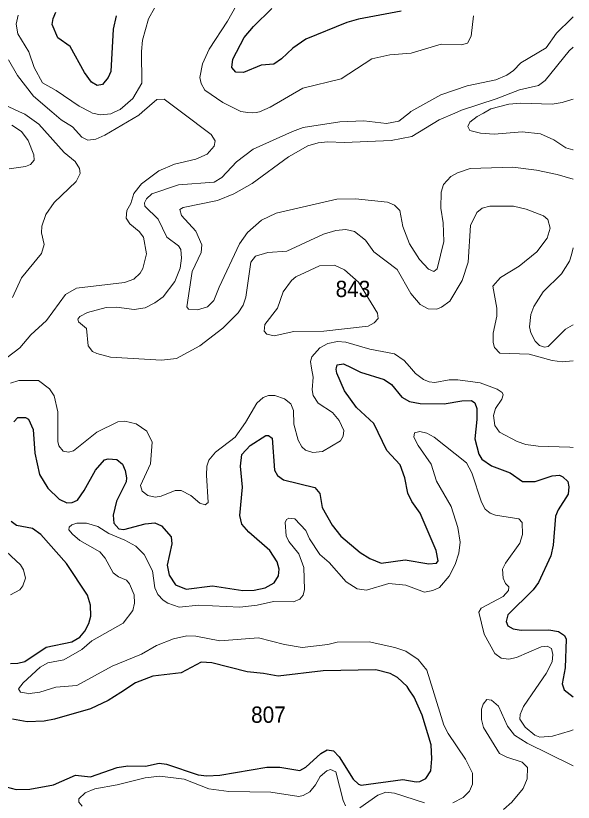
# Model space of a CAD drawing. Extents: x 473.9 to 500, y 7733.1 to 7760.8.
# Drawn here: x 497.268 to 500, y 7749.235 to 7753.088 of the extents above; entities that cross this region are included whole.
import ezdxf

# ---------------------------------------------------------------- set-up
doc = ezdxf.new("R2010")
doc.units = 0
doc.header["$LTSCALE"] = 0.032
doc.layers.add('1', color=7, linetype='Continuous', lineweight=25)
doc.layers.add('2', color=7, linetype='Continuous', lineweight=13)
doc.layers.add('21', color=7, linetype='Continuous')

msp = doc.modelspace()

# ---------------------------------------------------------------- linework, layer by layer
at = {"layer": '1'}
for points in [[(499.156, 7753.1103), (498.9468, 7753.0713), (498.8898, 7753.0552), (498.6902, 7752.9731), (498.6264, 7752.9292), (498.5701, 7752.8759), (498.5325, 7752.8503), (498.4698, 7752.8462), (498.3835, 7752.8103), (498.347, 7752.8107), (498.3273, 7752.8336), (498.3314, 7752.875), (498.3874, 7752.9803), (498.433, 7753.0351), (498.5221, 7753.1231)], [(497.7601, 7753.088), (497.7457, 7753.0212), (497.7334, 7752.8147), (497.7215, 7752.7859), (497.6934, 7752.7515), (497.667, 7752.7463), (497.6385, 7752.7631), (497.605, 7752.8093), (497.5349, 7752.9366), (497.4744, 7752.9793), (497.4469, 7753.0441), (497.4507, 7753.0734), (497.4647, 7753.1049)], [(499.1763, 7750.4223), (499.2926, 7750.4031), (499.329, 7750.4065), (499.3385, 7750.4175), (499.3286, 7750.4687), (499.2497, 7750.6503), (499.2096, 7750.7081), (499.1889, 7750.7494), (499.1751, 7750.824), (499.1514, 7750.8883), (499.0867, 7750.9575), (499.0231, 7751.0908), (498.938, 7751.1688), (498.8793, 7751.2502), (498.8413, 7751.3367), (498.838, 7751.3557), (498.8396, 7751.3631), (498.8426, 7751.3771), (498.8746, 7751.3821), (498.9117, 7751.3644), (498.9573, 7751.3425), (499.073, 7751.3062), (499.1087, 7751.281), (499.1606, 7751.2193), (499.1978, 7751.1974), (499.2491, 7751.1884), (499.3666, 7751.1862), (499.4542, 7751.2016), (499.501, 7751.2029), (499.5182, 7751.1919), (499.5267, 7751.1642), (499.5276, 7751.1106), (499.5182, 7751.0149), (499.5369, 7750.9398), (499.5523, 7750.9157), (499.5991, 7750.8836), (499.6915, 7750.8489), (499.7513, 7750.806), (499.8131, 7750.8059), (499.8968, 7750.8332), (499.932, 7750.8364), (499.9489, 7750.8298), (499.973, 7750.8058), (499.9787, 7750.7793), (499.9756, 7750.7446), (499.9252, 7750.6674), (499.9126, 7750.6366), (499.9014, 7750.4941), (499.8903, 7750.4423), (499.8302, 7750.312), (499.8034, 7750.2761), (499.6786, 7750.1527), (499.6715, 7750.1197), (499.6793, 7750.0996), (499.7059, 7750.0843), (499.7439, 7750.0775), (499.8806, 7750.0802), (499.9272, 7750.0709), (499.9572, 7750.0512), (499.9651, 7750.0342), (499.9595, 7749.894), (499.9458, 7749.8143), (499.9555, 7749.7854), (500, 7749.751)], [(497.258, 7751.0977), (497.2787, 7751.1202), (497.315, 7751.12), (497.3305, 7751.1107), (497.3537, 7751.0601), (497.3613, 7750.9448), (497.3836, 7750.84), (497.4246, 7750.7731), (497.4802, 7750.7192), (497.5175, 7750.7014), (497.5451, 7750.7032), (497.5698, 7750.7155), (497.6039, 7750.7622), (497.658, 7750.8624), (497.7026, 7750.912), (497.7203, 7750.917), (497.7632, 7750.9144), (497.7908, 7750.8915), (497.8046, 7750.8597), (497.8109, 7750.8246), (497.8082, 7750.8052), (497.7614, 7750.7094), (497.7452, 7750.641), (497.7478, 7750.6017), (497.7723, 7750.5751), (497.7976, 7750.5711), (497.9016, 7750.5981), (497.9488, 7750.6032), (497.982, 7750.5887), (498.0296, 7750.5356), (498.0321, 7750.5015), (498.0091, 7750.3961), (498.0202, 7750.3469), (498.0502, 7750.3002), (498.1027, 7750.2791), (498.2314, 7750.2946), (498.3806, 7750.2722), (498.4364, 7750.2738), (498.4893, 7750.2853), (498.5335, 7750.3094), (498.5555, 7750.3443), (498.5595, 7750.3767), (498.5485, 7750.4122), (498.5123, 7750.4675), (498.4104, 7750.5579), (498.3753, 7750.5972), (498.3659, 7750.6388), (498.3787, 7750.7787), (498.3692, 7750.8809), (498.3757, 7750.9378), (498.416, 7750.9828), (498.4927, 7751.0309), (498.5057, 7751.0307), (498.5236, 7751.0191), (498.5361, 7750.8618), (498.5504, 7750.8352), (498.5796, 7750.8141), (498.7337, 7750.7765), (498.7587, 7750.7466), (498.7689, 7750.6791), (498.8186, 7750.592), (498.8614, 7750.5386), (498.9555, 7750.4589), (499.0038, 7750.429), (499.0582, 7750.4063), (499.1763, 7750.4223)], [(497.2421, 7749.9153), (497.2775, 7749.9157), (497.3126, 7749.9247), (497.4161, 7749.9939), (497.5421, 7750.0207), (497.5811, 7750.0429), (497.6056, 7750.0724), (497.6253, 7750.1105), (497.6351, 7750.1471), (497.6348, 7750.2001), (497.6189, 7750.2487), (497.516, 7750.4038), (497.3913, 7750.5469), (497.3504, 7750.5754), (497.2723, 7750.5902), (497.2453, 7750.6096)], [(497.221, 7749.3104), (497.2695, 7749.2977), (497.337, 7749.2983), (497.4522, 7749.3198), (497.5613, 7749.3679), (497.6346, 7749.3587), (497.7645, 7749.4052), (497.8169, 7749.4133), (497.9043, 7749.4118), (497.9713, 7749.426), (498.0069, 7749.421), (498.1616, 7749.3699), (498.2049, 7749.3638), (498.2672, 7749.3673), (498.4977, 7749.4076), (498.5621, 7749.4076), (498.6594, 7749.3899), (498.6896, 7749.406), (498.7636, 7749.474), (498.7947, 7749.491), (498.8252, 7749.4871), (498.8527, 7749.4579), (498.9215, 7749.3475), (498.9472, 7749.3231), (498.961, 7749.3186), (499.1653, 7749.3472), (499.2305, 7749.3348), (499.2481, 7749.3369), (499.2773, 7749.3512), (499.3018, 7749.3886), (499.3074, 7749.4475), (499.3029, 7749.516), (499.2588, 7749.6621), (499.2207, 7749.7499), (499.1964, 7749.7861), (499.1857, 7749.802), (499.138, 7749.8455), (499.1032, 7749.866), (499.0318, 7749.8841), (498.7737, 7749.8795), (498.554, 7749.8524), (498.4826, 7749.866), (498.4025, 7749.873), (498.2292, 7749.9182), (498.1762, 7749.9214), (498.078, 7749.8692), (497.9391, 7749.8522), (497.8544, 7749.8206), (497.7821, 7749.7729), (497.721, 7749.7326), (497.6339, 7749.6928), (497.4575, 7749.6418), (497.4067, 7749.6322), (497.3232, 7749.6288), (497.2526, 7749.6416)]]:
    msp.add_lwpolyline(points, dxfattribs=at)
at = {"layer": '2'}
for points in [[(499.5107, 7753.0879), (499.5001, 7752.9877), (499.4809, 7752.9536), (499.4529, 7752.9446), (499.3522, 7752.9478), (499.2051, 7752.904), (499.1008, 7752.8963), (499.0132, 7752.8765), (498.8621, 7752.7779), (498.6752, 7752.7333), (498.5146, 7752.6391), (498.4623, 7752.6166), (498.4453, 7752.6142), (498.428, 7752.6118), (498.4057, 7752.6143), (498.3702, 7752.6184), (498.2834, 7752.6623), (498.1947, 7752.7236), (498.1772, 7752.7552), (498.1697, 7752.7851), (498.1834, 7752.8521), (498.2164, 7752.9244), (498.3056, 7753.0618), (498.39, 7753.2123)], [(497.9487, 7753.1282), (497.9182, 7753.0723), (497.8897, 7752.9685), (497.8843, 7752.9127), (497.8856, 7752.7569), (497.8412, 7752.6829), (497.7793, 7752.6282), (497.7533, 7752.6164), (497.7339, 7752.6075), (497.683, 7752.6021), (497.6444, 7752.6107), (497.6327, 7752.6167), (497.579, 7752.6443), (497.4659, 7752.7223), (497.3985, 7752.7598), (497.3582, 7752.8334), (497.3312, 7752.9115), (497.2777, 7752.999), (497.2692, 7753.0472), (497.279, 7753.09)], [(497.3816, 7752.557), (497.3127, 7752.6061), (497.2866, 7752.6178), (497.1761, 7752.6673), (497.1512, 7752.6865), (497.0837, 7752.7953), (497.0645, 7752.852), (497.0497, 7752.9648), (497.0587, 7753.0514), (497.041, 7753.1089)], [(500, 7751.3971), (499.9461, 7751.3924), (499.8971, 7751.3987), (499.7831, 7751.4297), (499.6393, 7751.4344), (499.6133, 7751.4624), (499.6072, 7751.4874), (499.6076, 7751.5324), (499.6249, 7751.6155), (499.6257, 7751.6554), (499.6062, 7751.763), (499.6432, 7751.8047), (499.7348, 7751.8603), (499.8219, 7751.9306), (499.8722, 7751.9977), (499.8869, 7752.0464), (499.8751, 7752.0888), (499.854, 7752.108), (499.7691, 7752.1407), (499.7073, 7752.1551), (499.5909, 7752.1555), (499.5533, 7752.1457), (499.5278, 7752.1243), (499.4971, 7752.0603), (499.4849, 7751.8809), (499.4553, 7751.7909), (499.3946, 7751.69), (499.3548, 7751.6598), (499.331, 7751.6507), (499.2893, 7751.6521), (499.2491, 7751.6739), (499.2045, 7751.7272), (499.1369, 7751.8454), (499.0232, 7751.9311), (498.9817, 7751.9886), (498.9273, 7752.0309), (498.8858, 7752.0407), (498.8371, 7752.036), (498.7761, 7752.0174), (498.5958, 7751.9348), (498.5038, 7751.9279), (498.4432, 7751.9095), (498.4202, 7751.8808), (498.3953, 7751.709), (498.3816, 7751.6697), (498.3578, 7751.6327), (498.2824, 7751.5577), (498.1702, 7751.4703), (498.0559, 7751.4092), (497.9819, 7751.4009), (497.7328, 7751.416), (497.6651, 7751.4324), (497.6435, 7751.4432), (497.623, 7751.47), (497.6138, 7751.5559), (497.5746, 7751.5884), (497.5716, 7751.602), (497.5816, 7751.6151), (497.6198, 7751.6348), (497.7111, 7751.6583), (497.7612, 7751.6597), (497.8475, 7751.6485), (497.9014, 7751.6565), (497.9502, 7751.6813), (497.9896, 7751.7114), (498.0477, 7751.7865), (498.0731, 7751.8504), (498.0804, 7751.9005), (498.0763, 7751.9424), (498.0651, 7751.9602), (498.0084, 7752.0028), (497.965, 7752.0904), (497.9, 7752.1552), (497.8993, 7752.1706), (497.9082, 7752.1905), (497.9352, 7752.2157), (498.0652, 7752.2595), (498.2408, 7752.2728), (498.2774, 7752.295), (498.3494, 7752.3718), (498.4318, 7752.4336), (498.6236, 7752.521), (498.6768, 7752.5395), (498.8563, 7752.5682), (498.9734, 7752.5731), (499.0842, 7752.5602), (499.1457, 7752.5718), (499.1969, 7752.6119), (499.2047, 7752.618), (499.3505, 7752.7004), (499.4803, 7752.7443), (499.6205, 7752.7738), (499.6743, 7752.7965), (499.7069, 7752.8192), (499.7435, 7752.8575), (499.8669, 7752.931), (499.917, 7753.0016), (499.9917, 7753.0749), (500, 7753.083)], [(500, 7752.9342), (499.9803, 7752.9161), (499.8625, 7752.7697), (499.8303, 7752.7457), (499.7364, 7752.7244), (499.6223, 7752.6805), (499.4519, 7752.6256), (499.4198, 7752.6112), (499.3434, 7752.5771), (499.2096, 7752.4967), (499.1072, 7752.4767), (498.8794, 7752.4669), (498.7963, 7752.4701), (498.7501, 7752.4652), (498.6993, 7752.451), (498.6038, 7752.3962), (498.4257, 7752.2665), (498.3363, 7752.2151), (498.256, 7752.1834), (498.0883, 7752.1486), (498.0717, 7752.1392), (498.0797, 7752.1085), (498.1511, 7752.032), (498.1793, 7751.9655), (498.1762, 7751.9284), (498.1327, 7751.8353), (498.1056, 7751.6619), (498.1147, 7751.651), (498.1579, 7751.6477), (498.2071, 7751.6624), (498.239, 7751.6923), (498.2643, 7751.7581), (498.3647, 7751.9704), (498.4036, 7752.026), (498.4723, 7752.0857), (498.5443, 7752.1212), (498.8409, 7752.1885), (498.933, 7752.1903), (499.0895, 7752.1743), (499.1246, 7752.1595), (499.1507, 7752.1342), (499.1651, 7752.0561), (499.1973, 7751.971), (499.2472, 7751.8941), (499.2913, 7751.8457), (499.3174, 7751.8352), (499.3334, 7751.8483), (499.3659, 7751.9821), (499.3628, 7752.0728), (499.3517, 7752.1451), (499.3534, 7752.2237), (499.3647, 7752.2607), (499.4003, 7752.3), (499.432, 7752.3181), (499.4953, 7752.3392), (499.7043, 7752.3456), (499.8201, 7752.3318), (499.9203, 7752.3108), (500, 7752.2867)], [(497.233, 7752.8715), (497.2769, 7752.7954), (497.3556, 7752.6942), (497.445, 7752.6173), (497.4906, 7752.5781), (497.5462, 7752.5437), (497.5912, 7752.4932), (497.6207, 7752.4776), (497.6598, 7752.4836), (497.7049, 7752.5024), (497.8705, 7752.6006), (497.8881, 7752.6159), (497.9592, 7752.6779), (497.9954, 7752.6793), (498.0806, 7752.6153), (498.2259, 7752.5063), (498.245, 7752.4748), (498.2408, 7752.4489), (498.2064, 7752.41), (498.1499, 7752.3856), (498.0453, 7752.3611), (497.9682, 7752.3282), (497.8835, 7752.2643), (497.8463, 7752.2164), (497.8316, 7752.1686), (497.8125, 7752.1332), (497.8095, 7752.0959), (497.8272, 7752.0691), (497.8726, 7752.0315), (497.8939, 7752.0032), (497.9084, 7751.922), (497.8909, 7751.8492), (497.8772, 7751.8263), (497.8458, 7751.7973), (497.801, 7751.781), (497.5656, 7751.7539), (497.5121, 7751.7226), (497.4179, 7751.5953), (497.3411, 7751.5242), (497.2883, 7751.4604), (497.1896, 7751.3867)], [(500, 7752.6794), (499.9928, 7752.6771), (499.945, 7752.6619), (499.8962, 7752.6553), (499.7418, 7752.6591), (499.6845, 7752.6543), (499.5968, 7752.6314), (499.5593, 7752.6108), (499.5296, 7752.5945), (499.4924, 7752.5658), (499.4827, 7752.5454), (499.4929, 7752.5253), (499.5457, 7752.5119), (499.6127, 7752.5072), (499.7494, 7752.5183), (499.8388, 7752.5087), (499.9047, 7752.4791), (499.9632, 7752.441), (499.9973, 7752.4309), (500, 7752.4301)], [(497.2483, 7752.5522), (497.2961, 7752.5204), (497.3284, 7752.4763), (497.3561, 7752.4061), (497.3578, 7752.3796), (497.3396, 7752.3588), (497.3148, 7752.3494), (497.235, 7752.3384)], [(497.2517, 7751.7077), (497.2962, 7751.804), (497.394, 7751.9232), (497.4065, 7751.967), (497.3939, 7752.024), (497.3961, 7752.0565), (497.4153, 7752.1135), (497.4566, 7752.1728), (497.5646, 7752.2753), (497.5832, 7752.3154), (497.5801, 7752.3395), (497.5597, 7752.3739), (497.505, 7752.4184), (497.3816, 7752.557)], [(500, 7751.9514), (499.9906, 7751.9173), (499.9818, 7751.8854), (499.9424, 7751.8241), (499.8517, 7751.7345), (499.8064, 7751.6632), (499.7922, 7751.6246), (499.7857, 7751.5642), (499.7924, 7751.5336), (499.8136, 7751.4938), (499.8343, 7751.4728), (499.8592, 7751.4637), (499.8767, 7751.4671), (499.9626, 7751.5528), (499.9957, 7751.5714), (500, 7751.5738)], [(498.7498, 7751.1906), (498.7254, 7751.228), (498.7206, 7751.2548), (498.7252, 7751.3175), (498.7175, 7751.3611), (498.7117, 7751.3936), (498.7185, 7751.4166), (498.7576, 7751.4602), (498.7979, 7751.4816), (498.845, 7751.4917), (498.8858, 7751.4882), (499.0032, 7751.4538), (499.1247, 7751.4314), (499.1715, 7751.3992), (499.1974, 7751.3692), (499.2266, 7751.3354), (499.2653, 7751.3065), (499.2932, 7751.2941), (499.3209, 7751.2912), (499.3918, 7751.3035), (499.4336, 7751.3035), (499.5435, 7751.2888), (499.6265, 7751.2577), (499.6513, 7751.2414), (499.6561, 7751.2303), (499.6504, 7751.21), (499.619, 7751.1642), (499.6089, 7751.1293), (499.6161, 7751.0802), (499.6386, 7751.0483), (499.7257, 7751.0023), (499.7679, 7750.9882), (499.8275, 7750.9788), (499.9828, 7750.974), (500, 7750.9735)], [(497.2413, 7751.2879), (497.2832, 7751.3006), (497.38, 7751.3003), (497.4336, 7751.2598), (497.4557, 7751.2263), (497.4742, 7751.1476), (497.4733, 7751.0024), (497.4791, 7750.9815), (497.4999, 7750.955), (497.526, 7750.9498), (497.5516, 7750.9571), (497.6652, 7751.0473), (497.7688, 7751.0991), (497.803, 7751.1025), (497.8575, 7751.0879), (497.9095, 7751.0521), (497.9356, 7750.9991), (497.9277, 7750.8925), (497.8796, 7750.7858), (497.8867, 7750.7591), (497.9149, 7750.7368), (497.9506, 7750.7287), (497.9804, 7750.734), (498.0487, 7750.7619), (498.0787, 7750.7622), (498.1252, 7750.7374), (498.1698, 7750.6995), (498.1965, 7750.6911), (498.2115, 7750.7032), (498.2018, 7750.8377), (498.2041, 7750.8811), (498.2137, 7750.9107), (498.2464, 7750.9494), (498.3425, 7751.0238), (498.3939, 7751.0956), (498.4498, 7751.1899), (498.4795, 7751.2172), (498.5066, 7751.2279), (498.537, 7751.2274), (498.5845, 7751.2119), (498.6154, 7751.1866), (498.6286, 7751.1546), (498.6313, 7751.087), (498.6521, 7751.0084), (498.6704, 7750.9759), (498.6875, 7750.9602), (498.7234, 7750.9474), (498.7715, 7750.9536), (498.8598, 7751.006), (498.8726, 7751.0286), (498.8756, 7751.0556), (498.8528, 7751.1046), (498.8199, 7751.1442), (498.7498, 7751.1906)], [(500, 7749.5896), (499.9862, 7749.5853), (499.8989, 7749.5582), (499.8364, 7749.5533), (499.8118, 7749.5641), (499.7638, 7749.6025), (499.7382, 7749.6427), (499.7394, 7749.6655), (499.7568, 7749.7043), (499.8169, 7749.7919), (499.8674, 7749.8655), (499.8963, 7749.9226), (499.8992, 7749.9594), (499.8933, 7749.9873), (499.8723, 7750.0001), (499.8426, 7749.9955), (499.7213, 7749.9435), (499.685, 7749.936), (499.6465, 7749.9407), (499.6149, 7749.9629), (499.5638, 7750.0579), (499.5368, 7750.1654), (499.5484, 7750.1862), (499.6563, 7750.2428), (499.6825, 7750.2725), (499.6842, 7750.2899), (499.6678, 7750.3063), (499.6562, 7750.3329), (499.6539, 7750.3767), (499.6671, 7750.4053), (499.7375, 7750.5044), (499.7514, 7750.5463), (499.7497, 7750.6058), (499.7329, 7750.6233), (499.6188, 7750.6419), (499.5931, 7750.6518), (499.5681, 7750.6711), (499.5504, 7750.7048), (499.5035, 7750.8485), (499.4765, 7750.8971), (499.3186, 7751.0229), (499.283, 7751.0427), (499.2481, 7751.0503), (499.2217, 7751.0442), (499.2191, 7751.023), (499.2394, 7750.983), (499.3041, 7750.8903), (499.3294, 7750.8078), (499.4014, 7750.6844), (499.4339, 7750.5806), (499.4456, 7750.5086), (499.439, 7750.4554), (499.4215, 7750.3999), (499.3926, 7750.342), (499.3452, 7750.287), (499.3113, 7750.2716), (499.2702, 7750.264), (499.18, 7750.298), (499.0957, 7750.3066), (498.9871, 7750.2746), (498.9405, 7750.2798), (498.8865, 7750.315), (498.8045, 7750.409), (498.7577, 7750.4488), (498.7074, 7750.5259), (498.6887, 7750.5659), (498.6358, 7750.624), (498.6057, 7750.6259), (498.5948, 7750.6195), (498.5878, 7750.6054), (498.5928, 7750.5392), (498.6054, 7750.5122), (498.6559, 7750.4518), (498.6794, 7750.3847), (498.6826, 7750.2772), (498.6759, 7750.249), (498.6603, 7750.2294), (498.629, 7750.2173), (498.5302, 7750.2183), (498.4517, 7750.1998), (498.3654, 7750.1901), (498.1654, 7750.2003), (498.0694, 7750.1901), (498.013, 7750.2098), (497.9908, 7750.2242), (497.9646, 7750.2534), (497.9497, 7750.2854), (497.9373, 7750.3693), (497.8967, 7750.4486), (497.8563, 7750.4891), (497.802, 7750.5194), (497.7248, 7750.5508), (497.6694, 7750.5854), (497.6151, 7750.6016), (497.5672, 7750.6013), (497.5425, 7750.5947), (497.53, 7750.5821), (497.5283, 7750.5694), (497.5454, 7750.5474), (497.5822, 7750.5176)], [(497.5822, 7750.5176), (497.6799, 7750.4617), (497.7057, 7750.4312), (497.7446, 7750.3593), (497.7707, 7750.3388), (497.8111, 7750.3223), (497.8259, 7750.3054), (497.848, 7750.2503), (497.8496, 7750.2102), (497.842, 7750.1736), (497.7945, 7750.1129), (497.6401, 7750.0259), (497.5921, 7749.9829), (497.5029, 7749.933), (497.4246, 7749.9179), (497.3867, 7749.8973), (497.3038, 7749.8194), (497.2806, 7749.7903), (497.2908, 7749.7741), (497.3198, 7749.7686), (497.3315, 7749.7663), (497.3481, 7749.7688), (497.3855, 7749.7745), (497.4637, 7749.7984), (497.5673, 7749.8074), (497.7406, 7749.9023), (497.8848, 7749.9606), (497.957, 7750.0031), (498.0414, 7750.0359), (498.1069, 7750.0501), (498.1502, 7750.0487), (498.2683, 7750.026), (498.4569, 7750.0397), (498.585, 7750.0069), (498.6719, 7749.9923), (498.798, 7750.0075), (498.8424, 7750.0196), (499.0004, 7750.0204), (499.126, 7749.9935), (499.1794, 7749.9753), (499.2397, 7749.9343), (499.2818, 7749.8822), (499.3114, 7749.7872), (499.3658, 7749.6126), (499.3873, 7749.5713), (499.4721, 7749.4468), (499.5065, 7749.3778), (499.5066, 7749.3235), (499.4911, 7749.2899), (499.4609, 7749.259), (499.4101, 7749.232)], [(497.2429, 7750.2509), (497.2884, 7750.2754), (497.3033, 7750.2953), (497.3148, 7750.3319), (497.306, 7750.3739), (497.2916, 7750.3972), (497.1977, 7750.4842)], [(500, 7749.4138), (499.9926, 7749.4174), (499.774, 7749.5245), (499.7127, 7749.5632), (499.6773, 7749.6071), (499.6337, 7749.7059), (499.5993, 7749.7355), (499.5772, 7749.7381), (499.5577, 7749.7154), (499.5508, 7749.6913), (499.5503, 7749.6397), (499.5594, 7749.6017), (499.6387, 7749.4745), (499.6737, 7749.4552), (499.7489, 7749.431), (499.7751, 7749.4059), (499.7745, 7749.3498), (499.7552, 7749.3016), (499.6997, 7749.2356), (499.6579, 7749.1991)], [(498.8832, 7749.2174), (498.8719, 7749.2441), (498.8371, 7749.3846), (498.8106, 7749.3949), (498.7917, 7749.3886), (498.7602, 7749.3608), (498.7372, 7749.3203), (498.7085, 7749.2863), (498.6763, 7749.2684), (498.6549, 7749.2639), (498.518, 7749.2846), (498.3116, 7749.2872), (498.2134, 7749.3004), (498.0924, 7749.3486), (497.9745, 7749.3635), (497.9016, 7749.3552), (497.7643, 7749.3205), (497.6547, 7749.301), (497.6086, 7749.2806), (497.5762, 7749.2521), (497.5764, 7749.2361), (497.5938, 7749.2152)], [(499.2708, 7749.2323), (499.1244, 7749.2795), (499.082, 7749.2846), (499.0429, 7749.2694), (498.9543, 7749.2083)]]:
    msp.add_lwpolyline(points, dxfattribs=at)
msp.add_lwpolyline([(498.9471, 7751.7832), (498.8783, 7751.8434), (498.8304, 7751.8658), (498.7571, 7751.8621), (498.6398, 7751.8087), (498.6191, 7751.7907), (498.578, 7751.7356), (498.5506, 7751.6552), (498.4885, 7751.5759), (498.4849, 7751.5427), (498.498, 7751.5273), (498.534, 7751.519), (498.6312, 7751.5415), (498.7775, 7751.5424), (498.9944, 7751.5676), (499.0245, 7751.5833), (499.0444, 7751.6045), (499.041, 7751.631)], close=True, dxfattribs=at)

# ---------------------------------------------------------------- texts
at = {"layer": '21', "width": 0.95}
for s, p in [('843', (498.8355, 7751.7096)), ('807', (498.4213, 7749.624))]:
    msp.add_text(s, height=0.08, dxfattribs=at).set_placement(p)

doc.saveas('drawing.dxf')
